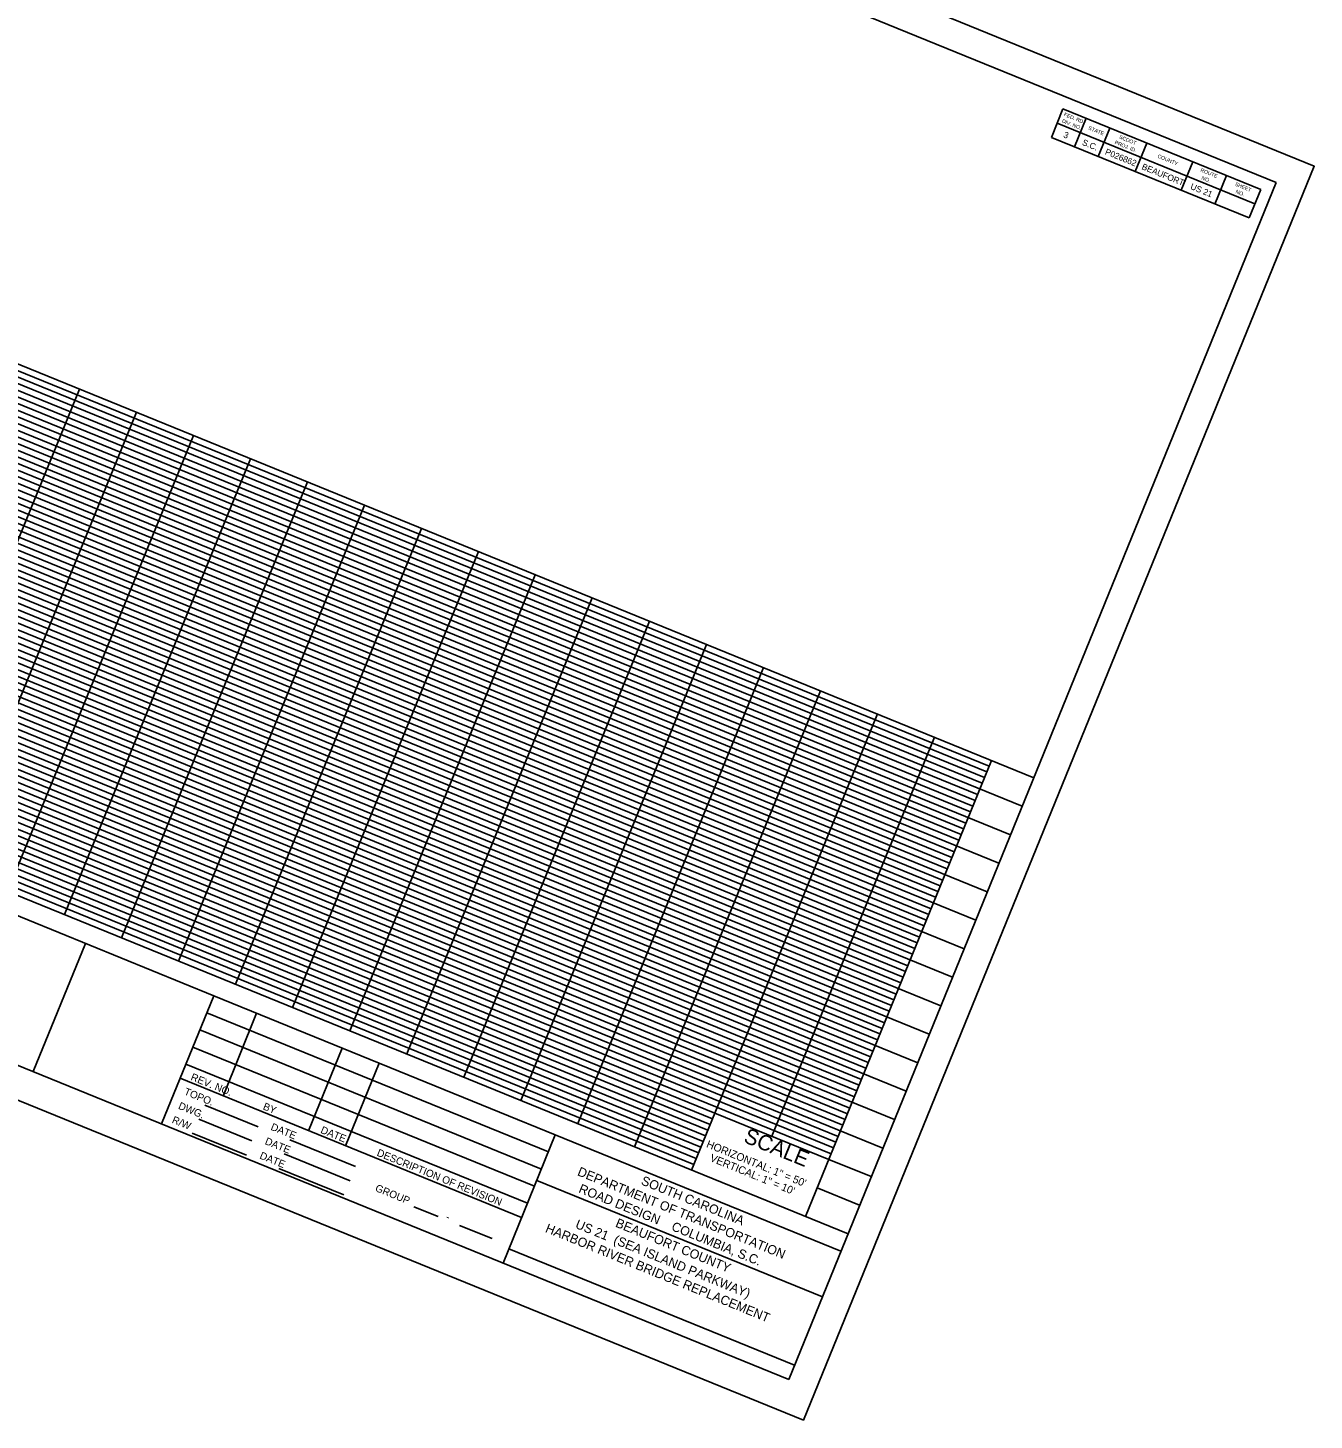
# Model space of a CAD drawing. Extents: x 2163359 to 2165441, y 212341 to 214039.
# Drawn here: x 2164396 to 2165441, y 212341 to 213472 of the extents above; entities that cross this region are included whole.
import ezdxf

# ---------------------------------------------------------------- set-up
doc = ezdxf.new("R2010")
doc.units = 0
for name, color, linetype in [('RD_SHT_Bndy', 7, 'Continuous'), ('RD_SHT_IplotShp', 7, 'Continuous'), ('RD_SHT_Misc1', 7, 'Continuous'), ('RD_SHT_Misc4', 7, 'Continuous'), ('RD_SHT_MjGrid', 7, 'Continuous'), ('RD_SHT_SubGrid', 7, 'Continuous'), ('RD_SHT_TX', 7, 'Continuous')]:
    doc.layers.add(name, color=color, linetype=linetype)

msp = doc.modelspace()

# ---------------------------------------------------------------- linework, layer by layer
at = {"layer": 'RD_SHT_Bndy'}
for p, q in [((2165410.5, 213346.7), (2163859.3, 213978.6)), ((2165237.3, 213406.5), (2165227.9, 213383.3)), ((2165237.3, 213406.5), (2165398, 213341)), ((2165232.6, 213394.9), (2165393.2, 213329.5)), ((2165256, 213398.9), (2165246.6, 213375.7)), ((2165227.9, 213383.3), (2165388.5, 213317.9)), ((2165275.3, 213391), (2165265.9, 213367.8)), ((2165305.5, 213378.7), (2165296, 213355.6)), ((2165342.7, 213363.6), (2165333.3, 213340.4)), ((2165370.2, 213352.4), (2165360.8, 213329.2)), ((2165014.5, 212374.3), (2165410.5, 213346.7)), ((2165398, 213341), (2165388.5, 213317.9)), ((2163463.2, 213006.1), (2165014.5, 212374.3)), ((2164504.9, 212581.8), (2164547.3, 212686)), ((2164547.3, 212686), (2165056.9, 212478.5)), ((2164541.7, 212672.1), (2164819.2, 212559.1)), ((2164554.9, 212604.5), (2164582.2, 212671.8)), ((2164536, 212658.2), (2164813.5, 212545.2)), ((2164530.4, 212644.3), (2164807.8, 212531.3)), ((2164624.3, 212576.2), (2164651.7, 212643.5)), ((2164524.7, 212630.5), (2164802.2, 212517.4)), ((2164654.4, 212564), (2164681.8, 212631.2)), ((2164520, 212618.9), (2164797.5, 212505.9)), ((2164540, 212597.2), (2164583.3, 212579.6)), ((2164535.3, 212585.7), (2164578.2, 212568.2)), ((2164529.8, 212574.4), (2164573.9, 212556.4)), ((2164609.2, 212569), (2164662.6, 212547.3)), ((2164782.4, 212468.8), (2164824.8, 212573)), ((2164604.5, 212557.5), (2164658.3, 212535.6)), ((2164600.2, 212545.7), (2164653.1, 212524.1)), ((2164809.7, 212536), (2165041.8, 212441.4)), ((2164709.8, 212514.6), (2164729.6, 212506.5)), ((2164747, 212499.4), (2164773.4, 212488.7)), ((2164787.1, 212480.4), (2165019.2, 212385.9))]:
    msp.add_line(p, q, dxfattribs=at)
for points in [[(2163662.3, 213494.9), (2165213.6, 212863.1)], [(2163511.4, 213124.5), (2165062.7, 212492.6)], [(2165028.2, 212506.7), (2165179.1, 212877.1)], [(2164935.6, 212544.4), (2164954.5, 212590.7)], [(2164954.5, 212590.7), (2165047.1, 212553)]]:
    msp.add_lwpolyline(points, dxfattribs=at)
at = {"layer": 'RD_SHT_IplotShp'}
msp.add_lwpolyline([(2163774.3, 214038.9), (2165441.4, 213359.9), (2165026.4, 212341.2), (2163359.4, 213020.1)], close=True, dxfattribs=at)
at = {"layer": 'RD_SHT_Misc4'}
for p, q in [((2164339, 212770.9), (2164547.3, 212686)), ((2164400.7, 212624.3), (2164443.2, 212728.5))]:
    msp.add_line(p, q, dxfattribs=at)
at = {"layer": 'RD_SHT_MjGrid'}
for p, q in [((2164438.2, 213178.9), (2164287.3, 212808.5)), ((2164484.5, 213160), (2164333.6, 212789.6)), ((2164530.8, 213141.2), (2164379.9, 212770.7)), ((2164577.1, 213122.3), (2164426.2, 212751.9)), ((2164623.4, 213103.5), (2164472.5, 212733)), ((2164669.7, 213084.6), (2164518.8, 212714.2)), ((2164716, 213065.7), (2164565.1, 212695.3)), ((2164762.3, 213046.9), (2164611.4, 212676.4)), ((2164808.6, 213028), (2164657.8, 212657.6)), ((2164854.9, 213009.2), (2164704.1, 212638.7)), ((2164901.3, 212990.3), (2164750.4, 212619.8)), ((2164947.6, 212971.4), (2164796.7, 212601)), ((2164993.9, 212952.6), (2164843, 212582.1)), ((2165040.2, 212933.7), (2164889.3, 212563.3)), ((2165086.5, 212914.9), (2164954.5, 212590.7)), ((2165132.8, 212896), (2165000.8, 212571.9))]:
    msp.add_line(p, q, dxfattribs=at)
for points in [[(2163652.9, 213471.8), (2165204.1, 212839.9)], [(2163643.4, 213448.6), (2165194.7, 212816.8)], [(2163634, 213425.5), (2165185.3, 212793.6)], [(2163624.6, 213402.3), (2165175.8, 212770.5)], [(2163615.1, 213379.2), (2165166.4, 212747.3)], [(2163605.7, 213356), (2165157, 212724.2)], [(2163596.3, 213332.9), (2165147.5, 212701)], [(2163586.8, 213309.7), (2165138.1, 212677.9)], [(2163577.4, 213286.6), (2165128.7, 212654.7)], [(2163568, 213263.4), (2165119.3, 212631.6)], [(2163558.6, 213240.2), (2165109.8, 212608.4)], [(2163549.1, 213217.1), (2165100.4, 212585.3)], [(2163539.7, 213193.9), (2165091, 212562.1)], [(2163530.3, 213170.8), (2164954.5, 212590.7)], [(2163520.8, 213147.6), (2164945, 212567.6)], [(2165047.1, 212553), (2165081.5, 212539)], [(2165037.6, 212529.8), (2165072.1, 212515.8)]]:
    msp.add_lwpolyline(points, dxfattribs=at)
at = {"layer": 'RD_SHT_SubGrid'}
for p, q in [((2165177.2, 212872.5), (2163695.4, 213476)), ((2165171.5, 212858.6), (2163689.7, 213462.2)), ((2165173.4, 212863.2), (2163691.6, 213466.8)), ((2165175.3, 212867.9), (2163693.5, 213471.4)), ((2165167.8, 212849.4), (2163686, 213452.9)), ((2165162.1, 212835.5), (2163680.3, 213439)), ((2165164, 212840.1), (2163682.2, 213443.6)), ((2165165.9, 212844.7), (2163684.1, 213448.3)), ((2165158.3, 212826.2), (2163676.5, 213429.7)), ((2165152.7, 212812.3), (2163670.9, 213415.8)), ((2165154.6, 212816.9), (2163672.8, 213420.5)), ((2165156.5, 212821.6), (2163674.7, 213425.1)), ((2165148.9, 212803), (2163667.1, 213406.6)), ((2165145.1, 212793.8), (2163663.3, 213397.3)), ((2165147, 212798.4), (2163665.2, 213402)), ((2165139.5, 212779.9), (2163657.7, 213383.4)), ((2165143.3, 212789.2), (2163661.5, 213392.7)), ((2165135.7, 212770.6), (2163653.9, 213374.2)), ((2165137.6, 212775.3), (2163655.8, 213378.8)), ((2165130.1, 212756.7), (2163648.2, 213360.3)), ((2165133.8, 212766), (2163652, 213369.5)), ((2165126.3, 212747.5), (2163644.5, 213351)), ((2165128.2, 212752.1), (2163646.4, 213355.6)), ((2165120.6, 212733.6), (2163638.8, 213337.1)), ((2165124.4, 212742.8), (2163642.6, 213346.4)), ((2165116.8, 212724.3), (2163635, 213327.9)), ((2165118.7, 212729), (2163636.9, 213332.5)), ((2165111.2, 212710.4), (2163629.4, 213314)), ((2165115, 212719.7), (2163633.2, 213323.2)), ((2165107.4, 212701.2), (2163625.6, 213304.7)), ((2165109.3, 212705.8), (2163627.5, 213309.3)), ((2165105.5, 212696.5), (2163623.7, 213300.1)), ((2165098, 212678), (2163616.2, 213281.6)), ((2165099.9, 212682.6), (2163618.1, 213286.2)), ((2165101.8, 212687.3), (2163620, 213290.8)), ((2165096.1, 212673.4), (2163614.3, 213276.9)), ((2165088.6, 212654.9), (2163606.8, 213258.4)), ((2165090.4, 212659.5), (2163608.6, 213263)), ((2165092.3, 212664.1), (2163610.5, 213267.7)), ((2165086.7, 212650.2), (2163604.9, 213253.8)), ((2165079.1, 212631.7), (2163597.3, 213235.3)), ((2165081, 212636.3), (2163599.2, 213239.9)), ((2165082.9, 212641), (2163601.1, 213244.5)), ((2165077.2, 212627.1), (2163595.4, 213230.6)), ((2165069.7, 212608.6), (2163587.9, 213212.1)), ((2165071.6, 212613.2), (2163589.8, 213216.7)), ((2165073.5, 212617.8), (2163591.7, 213221.4)), ((2165067.8, 212603.9), (2163586, 213207.5)), ((2165062.2, 212590), (2163580.4, 213193.6)), ((2165064, 212594.7), (2163582.2, 213198.2)), ((2165058.4, 212580.8), (2163576.6, 213184.3)), ((2165060.3, 212585.4), (2163578.5, 213188.9)), ((2165052.7, 212566.9), (2163570.9, 213170.4)), ((2165054.6, 212571.5), (2163572.8, 213175.1)), ((2165049, 212557.6), (2163567.1, 213161.2)), ((2165050.8, 212562.3), (2163569, 213165.8)), ((2164950.7, 212581.5), (2163561.5, 213147.3)), ((2164952.6, 212586.1), (2163563.4, 213151.9)), ((2164946.9, 212572.2), (2163557.7, 213138)), ((2164948.8, 212576.8), (2163559.6, 213142.6)), ((2164941.2, 212558.3), (2163552.1, 213124.1)), ((2164943.1, 212562.9), (2163553.9, 213128.7)), ((2164937.5, 212549), (2163548.3, 213114.9)), ((2164939.4, 212553.7), (2163550.2, 213119.5))]:
    msp.add_line(p, q, dxfattribs=at)

# ---------------------------------------------------------------- texts
at = {"layer": 'RD_SHT_Misc1'}
for s, height, p in [('HORIZONTAL: 1" = 50\'', 6.25, (2164947, 212563.1)), ('SCALE', 12.5, (2164977, 212567.3)), ('VERTICAL: 1" = 10\'', 6.25, (2164949.8, 212551.9))]:
    msp.add_text(s, height=height, rotation=337.8388, dxfattribs=at).set_placement(p)
at = {"layer": 'RD_SHT_TX'}
for s, height, p in [('DIV. NO.', 3, (2165236.1, 213395.7)), ('FED. RD.', 3, (2165237.7, 213400.9)), ('3', 5, (2165237.2, 213383.6)), ('S.C.', 5, (2165252.4, 213377.4)), ('STATE', 3, (2165257.6, 213389.9)), ('SCDOT', 3, (2165282.7, 213382.6)), ('P026862', 5, (2165271, 213369.8)), ('PROJ. ID.', 3, (2165279, 213378.2)), ('BEAUFORT', 5, (2165300.8, 213357.7)), ('COUNTY', 3, (2165313.8, 213367)), ('ROUTE', 3, (2165348.7, 213355.7)), ('NO.', 3, (2165349.5, 213349.4)), ('US 21', 5, (2165340.3, 213341.6)), ('SHEET', 3, (2165376.7, 213344.3)), ('NO.', 3, (2165377.2, 213338.2)), ('REV. NO.', 6, (2164528.1, 212617.7)), ('TOPO.', 6, (2164522.7, 212605.9)), ('DWG.', 6, (2164518, 212594.3)), ('BY', 6, (2164586.8, 212593.8)), ('R/W', 6, (2164512.9, 212582.9)), ('DATE', 6, (2164593.1, 212577.2)), ('DATE', 6, (2164633.6, 212574.7)), ('DATE', 6, (2164588.4, 212565.6)), ('DATE', 6, (2164584.1, 212553.9)), ('DESCRIPTION OF REVISION', 6, (2164679.3, 212556.2)), ('DEPARTMENT OF TRANSPORTATION', 7.5, (2164842.2, 212540.3)), ('ROAD DESIGN    COLUMBIA, S.C.', 7.5, (2164843.2, 212526.4)), ('SOUTH CAROLINA', 7.5, (2164893.9, 212532.9)), ('GROUP', 6, (2164678, 212527.5)), ('-', 6, (2164735.4, 212504.1)), ('HARBOR RIVER BRIDGE REPLACEMENT', 7.5, (2164816.1, 212494.2)), ('US 21  (SEA ISLAND PARKWAY)', 7.5, (2164840.5, 212497.5)), ('BEAUFORT COUNTY', 7.5, (2164873.1, 212498.5))]:
    msp.add_text(s, height=height, rotation=337.8388, dxfattribs=at).set_placement(p)

doc.saveas('drawing.dxf')
